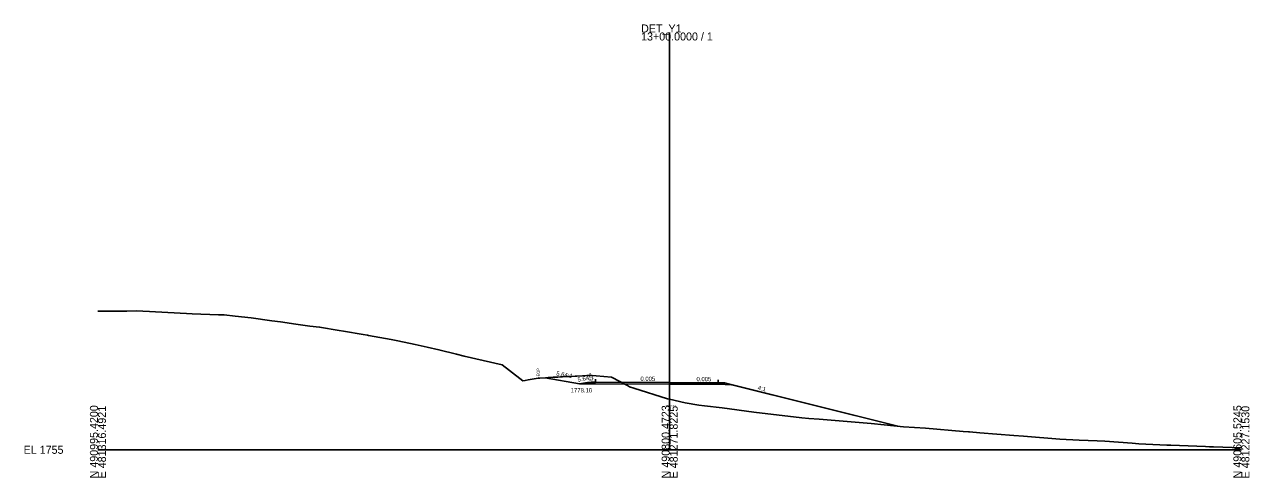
# Model space of a CAD drawing. Extents: x -26 to 403, y -10 to 3149.
# Drawn here: x -25.7 to 402.8, y 2990.3 to 3148.9 of the extents above; entities that cross this region are included whole.
import ezdxf

# ---------------------------------------------------------------- set-up
doc = ezdxf.new("R2010")
doc.units = 0
for name, color, linetype in [('Exist Cross Section Cell', 7, 'Continuous'), ('Exist XS Center Line Elevation Label', 7, 'Continuous'), ('Exist XS Ground Line', 7, 'Continuous'), ('Prop XS Ditch Slope Text', 7, 'Continuous'), ('Prop XS Ditch Standard Text', 7, 'Continuous'), ('Prop XS Dump Level', 7, 'Continuous'), ('Prop XS EOT Tick Mark', 7, 'Continuous'), ('Prop XS Finish Grade', 7, 'Continuous'), ('Prop XS Finish Grade Earthwork', 7, 'Continuous'), ('Prop XS Finish Grade Pavement', 7, 'Continuous'), ('Prop XS Pvmt Edge Slope', 7, 'Continuous'), ('Prop XS SE Text', 7, 'Continuous'), ('Prop XS Side Slope Text', 7, 'Continuous'), ('Prop XS Subgrade Earthwork', 7, 'Continuous'), ('Scratch_Level_3', 7, 'Continuous'), ('Scratch_Level_4', 7, 'Continuous')]:
    doc.layers.add(name, color=color, linetype=linetype)

msp = doc.modelspace()

# ---------------------------------------------------------------- linework, layer by layer
at = {"layer": 'Exist Cross Section Cell'}
for p, q in [((200, 3000), (200, 3146.08)), ((0, 3000), (200, 3000)), ((200, 3000), (400, 3000))]:
    msp.add_line(p, q, dxfattribs=at)
at = {"layer": 'Exist XS Ground Line'}
msp.add_lwpolyline([(0, 3048.54), (10.13, 3048.59), (13.35, 3048.69), (17.98, 3048.37), (24.47, 3048.09), (30.97, 3047.67), (32.94, 3047.64), (42.17, 3047.23), (42.98, 3047.23), (44.17, 3047.27), (47.99, 3046.8), (53.55, 3046.15), (60.86, 3045.17), (63.81, 3044.79), (69.21, 3044.03), (74.08, 3043.33), (77.56, 3042.95), (84.34, 3041.78), (85.91, 3041.51), (92.77, 3040.38), (94.26, 3040.14), (94.6, 3040.07), (102.61, 3038.58), (104.86, 3038.11), (110.95, 3036.83), (115.12, 3035.94), (119.3, 3035.03), (125.38, 3033.5), (128.07, 3032.75), (141.35, 3029.77), (143.98, 3027.76), (148.6, 3024.2), (149.4, 3024.32), (150.52, 3024.5), (154.02, 3025.08), (154.62, 3025.13), (156.73, 3025.25), (157.54, 3025.29), (159.3, 3025.38), (160.86, 3025.46), (161.86, 3025.51), (162.5, 3025.56), (163.66, 3025.65), (164.4, 3025.69), (165.2, 3025.72), (166.95, 3025.8), (167.48, 3025.83), (169.52, 3025.93), (171.06, 3026), (171.8, 3026.03), (172.41, 3026.04), (174.29, 3025.9), (179.68, 3025.44), (185.28, 3022.5), (185.97, 3022.07), (187.42, 3021.59), (199.22, 3017.89), (200, 3017.71), (205.42, 3016.48), (210.16, 3015.65), (212.23, 3015.43), (218.34, 3014.71), (229.45, 3013.13), (246.19, 3011.25), (248.73, 3010.98), (252.26, 3010.7), (270.47, 3009.16), (275.09, 3008.72), (281.79, 3008.03), (289.48, 3007.56), (302.66, 3006.43), (304.52, 3006.29), (304.89, 3006.25), (308.5, 3005.97), (320.39, 3005.01), (323.83, 3004.75), (336.46, 3003.78), (343.29, 3003.42), (349.56, 3003.11), (352.27, 3003.01), (361.81, 3002.3), (364.16, 3002.13), (373.95, 3001.63), (374.6, 3001.61), (375.3, 3001.59), (387.48, 3001.19), (388.79, 3001.09), (390.23, 3001.05), (400, 3000.65)], dxfattribs=at)
at = {"layer": 'Prop XS Dump Level'}
for p, q in [((174.11, 3023.68), (200, 3023.55)), ((200, 3023.55), (216.99, 3023.47))]:
    msp.add_line(p, q, dxfattribs=at)
at = {"layer": 'Prop XS EOT Tick Mark'}
for p, q in [((174.11, 3023.68), (174.11, 3024.68)), ((216.99, 3023.47), (216.99, 3024.47))]:
    msp.add_line(p, q, dxfattribs=at)
at = {"layer": 'Prop XS Finish Grade'}
for p, q in [((171.29, 3023.6), (168.46, 3023.1)), ((174.11, 3023.68), (171.29, 3023.6)), ((216.99, 3023.47), (219.16, 3023.39)), ((219.16, 3023.39), (221.7, 3022.75))]:
    msp.add_line(p, q, dxfattribs=at)
at = {"layer": 'Prop XS Finish Grade Earthwork'}
for p, q in [((168.46, 3023.1), (156.45, 3025.23)), ((221.7, 3022.75), (279.77, 3008.24))]:
    msp.add_line(p, q, dxfattribs=at)
at = {"layer": 'Prop XS Finish Grade Pavement'}
for p, q in [((174.11, 3023.68), (200, 3023.55)), ((200, 3023.55), (216.99, 3023.47))]:
    msp.add_line(p, q, dxfattribs=at)
at = {"layer": 'Prop XS Pvmt Edge Slope'}
for p, q in [((174.11, 3023.68), (173.31, 3023.12)), ((216.99, 3023.47), (217.6, 3022.9))]:
    msp.add_line(p, q, dxfattribs=at)
at = {"layer": 'Prop XS Subgrade Earthwork'}
for p, q in [((174.11, 3023.12), (168.46, 3023.1)), ((200, 3023.01), (174.11, 3023.12)), ((216.99, 3022.93), (200, 3023.01)), ((216.99, 3022.93), (221.7, 3022.75))]:
    msp.add_line(p, q, dxfattribs=at)
at = {"layer": 'Scratch_Level_4'}
for p, q in [((168.46, 3023.1), (156.45, 3025.23)), ((171.29, 3023.6), (168.46, 3023.1)), ((172.79, 3023.65), (171.29, 3023.6)), ((174.11, 3023.68), (172.79, 3023.65)), ((174.11, 3023.68), (200, 3023.55)), ((200, 3023.55), (216.99, 3023.47)), ((216.99, 3023.47), (218.12, 3023.43)), ((218.12, 3023.43), (219.16, 3023.39)), ((219.16, 3023.39), (279.77, 3008.24))]:
    msp.add_line(p, q, dxfattribs=at)

# ---------------------------------------------------------------- texts
at = {"layer": 'Exist Cross Section Cell'}
for s, p in [('13+00.0000 / 1', (190, 3143.28)), ('DET_Y1', (190, 3146.08)), ('EL 1755', (-26, 2998.6))]:
    msp.add_text(s, height=2.8, dxfattribs=at).set_placement(p)
for s, p in [('N 490995.4200', (0, 2990)), ('E 481316.4921', (2.8, 2990)), ('N 490800.4723', (200, 2990)), ('E 481271.8225', (202.8, 2990)), ('N 490605.5245', (400, 2990)), ('E 481227.1530', (402.8, 2990))]:
    msp.add_text(s, height=2.8, rotation=90, dxfattribs=at).set_placement(p)
at = {"layer": 'Exist XS Center Line Elevation Label'}
msp.add_text('1772.71', height=0.75, dxfattribs=at).set_placement((198.46, 3014.96))
at = {"layer": 'Prop XS Ditch Slope Text'}
msp.add_text('5.64:1', height=1.5, rotation=10.0481, dxfattribs=at).set_placement((167.94, 3023.8))
at = {"layer": 'Prop XS Ditch Standard Text'}
msp.add_text('1778.10', height=1.5, dxfattribs=at).set_placement((165.38, 3020.1))
at = {"layer": 'Prop XS SE Text'}
for rotation, p in [(359.7134, (189.77, 3024.13)), (359.7132, (209.38, 3024.02))]:
    msp.add_text('0.005', height=1.5, rotation=rotation, dxfattribs=at).set_placement(p)
at = {"layer": 'Prop XS Side Slope Text'}
for s, rotation, p in [('5.64:1', 349.9519, (160.24, 3026.08)), ('4:1', 345.9638, (230.7, 3021.1))]:
    msp.add_text(s, height=1.5, rotation=rotation, dxfattribs=at).set_placement(p)
at = {"layer": 'Scratch_Level_3'}
for p in [(154.52, 3025.24), (172.91, 3023.64)]:
    msp.add_text('-EOP', height=1, rotation=90, dxfattribs=at).set_placement(p)

doc.saveas('drawing.dxf')
